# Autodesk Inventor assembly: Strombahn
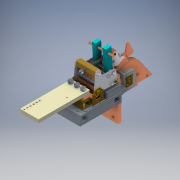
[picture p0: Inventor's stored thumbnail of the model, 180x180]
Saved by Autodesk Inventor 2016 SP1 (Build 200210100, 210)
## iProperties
Title: Strombahn
Comments: HSLT
Company: Mayer & Müller AG Schaltgeräte
Created: 2005-12
Part Number: 340853 Strombahn
Document SubType Name: Assembly
Designer: I.Baliuc
Manufacturer: Standard
Standards Organization: Custom
Description: Strombahn
Mass: 12082.3 g
Surface Area: 8161.82 cm^2
Volume: 2037 cm^3
Density: 5.93143 g/cm^3
Zweck: Vorkontakt HSLT
dX*dY*dZ: 110 x 526 x 296
Flaeche: 816182
Volumen: 2036999
Author: T.Messerschmitt
Revision Number: 340853
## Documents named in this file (62)
- D:\Inventor-Tools Tutorial\Baugruppen\340853 Strombahn.iam
- D:\Inventor-Tools Tutorial\Baugruppen\362517.iam
- D:\Inventor-Tools Tutorial\Bauteile\3\36\364835.ipt
- D:\Inventor-Tools Tutorial\Bauteile\3\36\366297.ipt
- D:\Inventor-Tools Tutorial\Bauteile\3\35\357419.ipt
- D:\Inventor-Tools Tutorial\Bauteile\3\35\356512.ipt
- D:\Inventor-Tools Tutorial\ContentCenter\DIN 125-1 A10 - St vz.ipt
- D:\Inventor-Tools Tutorial\Bauteile\3\36\361090.ipt
- D:\Inventor-Tools Tutorial\Bauteile\3\35\355018.ipt
- D:\Inventor-Tools Tutorial\Bauteile\3\35\356531.ipt
- D:\Inventor-Tools Tutorial\Bauteile\3\35\355073.ipt
- D:\Inventor-Tools Tutorial\Bauteile\3\35\356532.ipt
- D:\Inventor-Tools Tutorial\Bauteile\3\35\355104.ipt
- D:\Inventor-Tools Tutorial\Baugruppen\3\34\340827.iam
- D:\Inventor-Tools Tutorial\Bauteile\3\36\361570.ipt
- D:\Inventor-Tools Tutorial\ContentCenter\DIN 912 - M8x30 - 8.8 vz.ipt
- D:\Inventor-Tools Tutorial\ContentCenter\DIN 912 - M6x16 - A2.ipt
- D:\Inventor-Tools Tutorial\ContentCenter\DIN 934 - M8 - 8 vz.ipt
- D:\Inventor-Tools Tutorial\ContentCenter\DIN 127 - A6 - FSt vz.ipt
- D:\Inventor-Tools Tutorial\Bauteile\3\35\355017.ipt
- D:\Inventor-Tools Tutorial\ContentCenter\DIN 914 - M5x10 - 45H vz.ipt
- D:\Inventor-Tools Tutorial\ContentCenter\DIN 127 - A10 - FSt vz.ipt
- D:\Inventor-Tools Tutorial\ContentCenter\DIN 931-1 - M10x45 - 8.8 vz.ipt
- D:\Inventor-Tools Tutorial\Bauteile\3\35\357400.ipt
- D:\Inventor-Tools Tutorial\ContentCenter\DIN 912 - M8x12 - 8.8 vz.ipt
- D:\Inventor-Tools Tutorial\Baugruppen\3\34\340832.iam
- D:\Inventor-Tools Tutorial\Bauteile\3\37\378316.ipt
- D:\Inventor-Tools Tutorial\Bauteile\3\35\350860.ipt
- D:\Inventor-Tools Tutorial\Bauteile\3\35\350825_zu.ipt
- D:\Inventor-Tools Tutorial\ContentCenter\DIN 439 - M8 - 04 vz.ipt
- D:\Inventor-Tools Tutorial\ContentCenter\DIN 7991 - M6x16 - A2.ipt
- D:\Inventor-Tools Tutorial\ContentCenter\DIN 933 - M8x12 - 8.8 vz.ipt
- D:\Inventor-Tools Tutorial\ContentCenter\DIN 934 - M6 - 8 vz.ipt
- D:\Inventor-Tools Tutorial\ContentCenter\DIN 7991 - M10x40 - A2.ipt
- D:\Inventor-Tools Tutorial\Bauteile\3\36\360212_s.ipt
- D:\Inventor-Tools Tutorial\Bauteile\Ringfeder_N9.ipt
- D:\Inventor-Tools Tutorial\Bauteile\Ringfeder_N7.ipt
- D:\Inventor-Tools Tutorial\ContentCenter\DIN 912 - M6x35 - 8.8 vz.ipt
- D:\Inventor-Tools Tutorial\Bauteile\3\35\356578.ipt
- D:\Inventor-Tools Tutorial\Baugruppen\3\34\340855.iam
- D:\Inventor-Tools Tutorial\Baugruppen\3\34\340838.iam
- D:\Inventor-Tools Tutorial\Bauteile\3\36\366298.ipt
- D:\Inventor-Tools Tutorial\Bauteile\SPERRZSCHR_M8x12.ipt
- D:\Inventor-Tools Tutorial\Bauteile\SPERRZSCHR_M6x10.ipt
- D:\Inventor-Tools Tutorial\Bauteile\3\35\350822_C1.ipt
- D:\Inventor-Tools Tutorial\ContentCenter\DIN 6912 - M8x16 - A2.ipt
- D:\Inventor-Tools Tutorial\Bauteile\3\35\350822_C2.ipt
- D:\Inventor-Tools Tutorial\ContentCenter\DIN 127 - A6 - A2.ipt
- D:\Inventor-Tools Tutorial\Bauteile\3\36\360211.ipt
- D:\Inventor-Tools Tutorial\ContentCenter\DIN 9021 - 6.4 - A2.ipt
- D:\Inventor-Tools Tutorial\Baugruppen\3\34\340833.iam
- D:\Inventor-Tools Tutorial\Bauteile\3\37\378299.ipt
- D:\Inventor-Tools Tutorial\Bauteile\3\37\378333.ipt
- D:\Inventor-Tools Tutorial\Bauteile\3\36\361600.ipt
- D:\Inventor-Tools Tutorial\Baugruppen\3\34\342333.iam
- D:\Inventor-Tools Tutorial\ContentCenter\DIN 127 - A8 - FSt vz.ipt
- D:\Inventor-Tools Tutorial\ContentCenter\DIN 125-1 A10 - Ms.ipt
- D:\Inventor-Tools Tutorial\Bauteile\HMR_H10.ipt
- D:\Inventor-Tools Tutorial\Baugruppen\3\34\340831.iam
- D:\Inventor-Tools Tutorial\ContentCenter\DIN 125-1 A6 - St vz.ipt
- D:\Inventor-Tools Tutorial\ContentCenter\DIN 912 - M6x20 - A2.ipt
- D:\Inventor-Tools Tutorial\ContentCenter\DIN 912 - M6x25 - A2.ipt
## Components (126 placed, 67 different names)
1. 340838 - Hauptkontakt (mitte) [sub-assembly] — Einfügen:134, Einfügen:135
2. 340860 - Schiene, unten — Einfügen:94, Einfügen:95, Winkel:39, Winkel:46
3. 340831 - Stromschiene [sub-assembly] — Einfügen:89, Einfügen:90, Winkel:31, Einfügen:150, Einfügen:151, Winkel:62
4. 340832 - Vorkontakt [sub-assembly] — Einfügen:48, Einfügen:49, Tangential:1
5. 340833 - Funkenhorn, kompl. [sub-assembly] — Einfügen:70, Einfügen:73, Einfügen:74, Winkel:54, Winkel:63, Tangential:1
6. 340855 - Kontaktträger [sub-assembly] — Passend:24, Passend:25, Passend:26, Passend:27, Einfügen:48, Einfügen:49, Winkel:34, Winkel:53, Einfügen:158, Einfügen:159
7. 342333 - Spule, kompl. [sub-assembly] — Einfügen:66, Einfügen:67, Einfügen:68, Einfügen:69, Einfügen:70, Einfügen:73, Einfügen:74, Einfügen:76, Einfügen:89, Einfügen:90, Winkel:55, Winkel:56
8. 350825 - Stromband — Einfügen:22, Einfügen:23, Einfügen:94, Einfügen:95, Einfügen:134, Einfügen:135, Einfügen:139, Einfügen:140
9. 350822_C1 - Stromband — Einfügen:158, Einfügen:159, Fluchtend:4
10. 350822_C2 - Stromband — Fluchtend:4, Winkel:66
11. 355018 - Bolzen — Einfügen:24, Passend:22, Passend:23
12. 356531 - Bolzen — Einfügen:6
13. 355073 - Bolzen — Passend:5, Passend:40, Passend:41
14. 355017 - Bolzen — Einfügen:25, Passend:20, Passend:21, Passend:24, Passend:25
15. 355104 - Bolzen — Einfügen:145
16. 356512 - Gewindestange — Einfügen:17, Passend:32, Einfügen:119
17. 356578 - Bolzen — Passend:26, Passend:27, Passend:28, Passend:29
18. 356532 - Bolzen — Einfügen:5, Passend:8, Passend:31, Passend:43
19. 357400 - Welle — Passend:15, Passend:32
20. 357419 - Federsockel — Einfügen:17, Passend:28, Passend:29, Winkel:52, Fluchtend:3
21. 360212 - Druckfeder T1
22. 360212 - Druckfeder T2
23. 361600 - Gewindeplatte — Einfügen:68, Einfügen:69
24. 362469 - Isolator [sub-assembly] — Einfügen:148, Einfügen:149, Einfügen:150, Einfügen:151, Passend:51, Passend:52, Einfügen:152, Winkel:57
25. 364835 - Gewindeplatte — Einfügen:3, Passend:1
26. 366297 - Vierkantrohr — Einfügen:3, Passend:1, Einfügen:22, Einfügen:23, Einfügen:148, Einfügen:149, Winkel:58
27. 366298 - Distanzbuchse:1 — Passend:40, Passend:41
28. 378299 - Isolierplatte — Einfügen:66, Einfügen:67
29. DIN 125-1  A A 10.5:2
30. DIN 125-1  A A 10.5:1
31. DIN 912 - M6 x 20 - V2A:1 — Winkel:33, Winkel:34
32. DIN 912 - M6 x 25 - V2A:2 — Winkel:33, Winkel:53
33. DIN 914  M5 x 10:1 — Winkel:52, Fluchtend:3
34. Sperrzahnschraube_M6x10:1 — Winkel:43
35. Sperrzahnschraube_M6x10:2 — Winkel:60, Winkel:61
36. Sperrzahnschraube - M8x12:1 — Winkel:43, Winkel:64
37. Sperrzahnschraube - M8x12:2 — Winkel:60
38. DIN 933  - ersetzt durch DIN EN 24 017 M8 x 12:1 — Winkel:64, Winkel:65
39. DIN 933  - ersetzt durch DIN EN 24 017 M8 x 12:2 — Winkel:65
40. DIN 6912  M8 x 16:1 — Winkel:66
41. 361570_Kontaktträgerseitenteil:1 — Einfügen:5, Einfügen:6, Passend:5, Passend:15, Einfügen:24, Einfügen:25, Einfügen:152, Winkel:44, Winkel:45, Winkel:47, Winkel:48
42. 361570 - Kontaktträgerseitenteil:2 — Winkel:49, Winkel:50, Winkel:51, Winkel:61
43. DIN 7991 - ersetzt durch DIN EN ISO 10642  M10 x 40:2 — Winkel:31, Winkel:62
44. DIN 7991 - ersetzt durch DIN EN ISO 10642  M10 x 40:3
45. DIN 912  - ersetzt durch DIN EN ISO 4762 M8 x 30:1 — Winkel:58
46. DIN 934  - ersetzt durch DIN EN 24 032/28 673/28 674 M8:1 — Winkel:57
47. DIN 127 - zurückgezogen A 8:1
48. DIN 912  - ersetzt durch DIN EN ISO 4762 M8 x 30:2
49. DIN 934  - ersetzt durch DIN EN 24 032/28 673/28 674 M8:2
50. DIN 127 - zurückgezogen A 8:2
51. 361090_Lasche:1 — Einfügen:8, Passend:8, Passend:31
52. 361090:2 — Einfügen:96
53. 340827_Hauptkontakt:1 [sub-assembly] — Einfügen:8, Einfügen:139, Einfügen:140
54. 340827 - DC Hauptkontakt:2 [sub-assembly] — Passend:57
55. DIN 439-2  - ersetzt durch DIN EN 24 035/28 675 M8:2 — Einfügen:119, Winkel:44
56. DIN 439-2  - ersetzt durch DIN EN 24 035/28 675 M8:3
57. DIN 125-1  A A 10.5:6
58. DIN 127 - zurückgezogen A 10:4
59. DIN 931-1  - ersetzt durch DIN EN 24 014 M10 x 45:1 — Winkel:39
60. DIN 125-1  A A 10.5:7
61. DIN 127 - zurückgezogen A 10:5
62. DIN 931-1  - ersetzt durch DIN EN 24 014 M10 x 45:2
63. DIN 125-1  A A 10.5:8
64. DIN 127 - zurückgezogen A 10:6
65. DIN 931-1  - ersetzt durch DIN EN 24 014 M10 x 45:3 — Winkel:46
66. DIN 125-1  A A 6.4:11
67. DIN 127 - zurückgezogen A 6:13
68. DIN 934  - ersetzt durch DIN EN 24 032/28 673/28 674 M6:1 — Winkel:36, Winkel:45
69. DIN 912  - ersetzt durch DIN EN ISO 4762 M6 x 35:1 — Winkel:49
70. DIN 125-1  A A 6.4:13
71. DIN 127 - zurückgezogen A 6:15
72. DIN 934  - ersetzt durch DIN EN 24 032/28 673/28 674 M6:3 — Winkel:36, Winkel:37, Winkel:47
73. DIN 912  - ersetzt durch DIN EN ISO 4762 M6 x 35:3 — Winkel:32, Winkel:50
74. DIN 125-1  A A 6.4:15
75. DIN 127 - zurückgezogen A 6:17
76. DIN 934  - ersetzt durch DIN EN 24 032/28 673/28 674 M6:5 — Winkel:37, Winkel:48
77. DIN 912  - ersetzt durch DIN EN ISO 4762 M6 x 35:5 — Winkel:32, Winkel:51
78. DIN 125-1  A A 6.4:12
79. DIN 127 - zurückgezogen A 6:14
80. DIN 934  - ersetzt durch DIN EN 24 032/28 673/28 674 M6:2
81. DIN 912  - ersetzt durch DIN EN ISO 4762 M6 x 35:2
82. DIN 125-1  A A 6.4:14
83. DIN 127 - zurückgezogen A 6:16
84. DIN 934  - ersetzt durch DIN EN 24 032/28 673/28 674 M6:4
85. DIN 912  - ersetzt durch DIN EN ISO 4762 M6 x 35:4
86. DIN 125-1  A A 6.4:16
87. DIN 127 - zurückgezogen A 6:18
88. DIN 934  - ersetzt durch DIN EN 24 032/28 673/28 674 M6:6
89. DIN 912  - ersetzt durch DIN EN ISO 4762 M6 x 35:6
90. DIN 912  - ersetzt durch DIN EN ISO 4762 M8 x 12:1 — Passend:58
91. 360211_Druckfeder:4 — Passend:57, Passend:58
92. DIN 912  - ersetzt durch DIN EN ISO 4762 M8 x 12:2
93. 360211 - Druckfeder:5
94. DIN 912  - ersetzt durch DIN EN ISO 4762 M8 x 12:3
95. 360211 - Druckfeder:6
96. Ringfeder - N9:1 — Passend:20, Passend:21
97. Ringfeder - N9:2
98. Ringfeder - N7:1 — Passend:22, Passend:23
99. Ringfeder - N7:2
100. DIN 127 - zurückgezogen A 6:7
101. DIN 127 - zurückgezogen A 6:8
102. Halbmondring - H10:1
103. Halbmondring - H10:2
104. DIN 7991 - ersetzt durch DIN EN ISO 10642  M6 x 16:3 — Winkel:63
105. DIN 7991 - ersetzt durch DIN EN ISO 10642  M6 x 16:4 — Winkel:54
106. DIN 912  - ersetzt durch DIN EN ISO 4762 M6 x 16:2 — Winkel:56
107. DIN 127 - zurückgezogen A 6:3
108. DIN 912  - ersetzt durch DIN EN ISO 4762 M6 x 16:3
109. DIN 127 - zurückgezogen A 6:4
110. DIN 912  - ersetzt durch DIN EN ISO 4762 M6 x 16:4
111. DIN 127 - zurückgezogen A 6:5
112. DIN 912  - ersetzt durch DIN EN ISO 4762 M6 x 16:5
113. DIN 127 - zurückgezogen A 6:6
114. DIN 912  - ersetzt durch DIN EN ISO 4762 M6 x 25:4 — Winkel:55
115. DIN 127 - zurückgezogen A 6:1
116. DIN 9021 6.4:1
117. 378333 - Isolierhülse:1 — Einfügen:76
118. DIN 912  - ersetzt durch DIN EN ISO 4762 M6 x 25:5
119. DIN 127 - zurückgezogen A 6:2
120. DIN 9021 6.4:3
121. 378333_Isolierhülse:2
122. 360211_Druckfeder:1 — Passend:51, Passend:52
123. 360211 - Druckfeder:2
124. 360211 - Druckfeder:3
125. 378316 - Anschlaghebel — Passend:43, Einfügen:96, Einfügen:145
126. 378316:2
## Component patterns: 361570 - Kontaktträgerseitenteil (2 elements), DIN 7991 - M10 x 40 (2 elements), Schraube_01 (2 elements), 361090 - Lasche (2 elements), 340827 - Hauptkontakt (2 elements), DIN 439 - M8 (2 elements), KA 8 (3 elements), KA 9 (2 elements), KA 10 (3 elements), Ringfeder_N9 (2 elements), Ringfeder_N7 (2 elements), DIN 125-1 A6.4 (2 elements), Halbmondring_H10 (2 elements), 360211 - Druckfeder (3 elements), 378316 - Anschlaghebel (2 elements)
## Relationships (93: Insert 37, Angle 30, Mate 23, Flush 2, Tangent 1)
- Einfügen:3 [Insert]: 364835 - Gewindeplatte ↔ 366297 - Vierkantrohr
- Passend:1 [Mate]: 364835 - Gewindeplatte ↔ 366297 - Vierkantrohr
- Einfügen:5 [Insert]: 356532 - Bolzen ↔ 361570_Kontaktträgerseitenteil:1
- Einfügen:6 [Insert]: 356531 - Bolzen ↔ 361570_Kontaktträgerseitenteil:1
- Passend:5 [Mate]: 355073 - Bolzen ↔ 361570_Kontaktträgerseitenteil:1
- Einfügen:8 [Insert]: 361090_Lasche:1 ↔ 340827_Hauptkontakt:1
- Passend:8 [Mate]: 356532 - Bolzen ↔ 361090_Lasche:1
- Einfügen:17 [Insert]: 356512 - Gewindestange ↔ 357419 - Federsockel
- Passend:15 [Mate]: 357400 - Welle ↔ 361570_Kontaktträgerseitenteil:1
- Einfügen:22 [Insert]: 350825 - Stromband ↔ 366297 - Vierkantrohr
- Einfügen:23 [Insert]: 350825 - Stromband ↔ 366297 - Vierkantrohr
- Einfügen:24 [Insert]: 355018 - Bolzen ↔ 361570_Kontaktträgerseitenteil:1
- Einfügen:25 [Insert]: 355017 - Bolzen ↔ 361570_Kontaktträgerseitenteil:1
- Passend:20 [Mate]: 355017 - Bolzen ↔ Ringfeder - N9:1
- Passend:21 [Mate]: 355017 - Bolzen ↔ Ringfeder - N9:1
- Passend:22 [Mate]: 355018 - Bolzen ↔ Ringfeder - N7:1
- Passend:23 [Mate]: 355018 - Bolzen ↔ Ringfeder - N7:1
- Passend:24 [Mate]: 340855 - Kontaktträger ↔ 355017 - Bolzen
- Passend:25 [Mate]: 340855 - Kontaktträger ↔ 355017 - Bolzen
- Passend:26 [Mate]: 340855 - Kontaktträger ↔ 356578 - Bolzen
- Passend:27 [Mate]: 340855 - Kontaktträger ↔ 356578 - Bolzen
- Passend:28 [Mate]: 356578 - Bolzen ↔ 357419 - Federsockel
- Passend:29 [Mate]: 356578 - Bolzen ↔ 357419 - Federsockel
- Einfügen:48 [Insert]: 340832 - Vorkontakt ↔ 340855 - Kontaktträger
- Einfügen:49 [Insert]: 340832 - Vorkontakt ↔ 340855 - Kontaktträger
- Passend:31 [Mate]: 356532 - Bolzen ↔ 361090_Lasche:1
- Passend:32 [Mate]: 356512 - Gewindestange ↔ 357400 - Welle
- Einfügen:66 [Insert]: 342333 - Spule, kompl. ↔ 378299 - Isolierplatte
- Einfügen:67 [Insert]: 342333 - Spule, kompl. ↔ 378299 - Isolierplatte
- Einfügen:68 [Insert]: 342333 - Spule, kompl. ↔ 361600 - Gewindeplatte
- Einfügen:69 [Insert]: 342333 - Spule, kompl. ↔ 361600 - Gewindeplatte
- Einfügen:70 [Insert]: 340833 - Funkenhorn, kompl. ↔ 342333 - Spule, kompl.
- Einfügen:73 [Insert]: 340833 - Funkenhorn, kompl. ↔ 342333 - Spule, kompl.
- Einfügen:74 [Insert]: 340833 - Funkenhorn, kompl. ↔ 342333 - Spule, kompl.
- Einfügen:76 [Insert]: 342333 - Spule, kompl. ↔ 378333 - Isolierhülse:1
- Passend:40 [Mate]: 355073 - Bolzen ↔ 366298 - Distanzbuchse:1
- Passend:41 [Mate]: 355073 - Bolzen ↔ 366298 - Distanzbuchse:1
- Einfügen:89 [Insert]: 340831 - Stromschiene ↔ 342333 - Spule, kompl.
- Einfügen:90 [Insert]: 340831 - Stromschiene ↔ 342333 - Spule, kompl.
- Einfügen:94 [Insert]: 340860 - Schiene, unten ↔ 350825 - Stromband
- Einfügen:95 [Insert]: 340860 - Schiene, unten ↔ 350825 - Stromband
- Passend:43 [Mate]: 356532 - Bolzen ↔ 378316 - Anschlaghebel
- Einfügen:96 [Insert]: 361090:2 ↔ 378316 - Anschlaghebel
- Einfügen:119 [Insert]: 356512 - Gewindestange ↔ DIN 439-2  - ersetzt durch DIN EN 24 035/28 675 M8:2
- Winkel:31 [Angle]: 340831 - Stromschiene ↔ DIN 7991 - ersetzt durch DIN EN ISO 10642  M10 x 40:2
- Einfügen:134 [Insert]: 340838 - Hauptkontakt (mitte) ↔ 350825 - Stromband
- Einfügen:135 [Insert]: 340838 - Hauptkontakt (mitte) ↔ 350825 - Stromband
- Winkel:32 [Angle]: DIN 912  - ersetzt durch DIN EN ISO 4762 M6 x 35:3 ↔ DIN 912  - ersetzt durch DIN EN ISO 4762 M6 x 35:5
- Winkel:33 [Angle]: DIN 912 - M6 x 20 - V2A:1 ↔ DIN 912 - M6 x 25 - V2A:2
- Winkel:34 [Angle]: 340855 - Kontaktträger ↔ DIN 912 - M6 x 20 - V2A:1
- Einfügen:139 [Insert]: 350825 - Stromband ↔ 340827_Hauptkontakt:1
- Einfügen:140 [Insert]: 350825 - Stromband ↔ 340827_Hauptkontakt:1
- Winkel:36 [Angle]: DIN 934  - ersetzt durch DIN EN 24 032/28 673/28 674 M6:1 ↔ DIN 934  - ersetzt durch DIN EN 24 032/28 673/28 674 M6:3
- Winkel:37 [Angle]: DIN 934  - ersetzt durch DIN EN 24 032/28 673/28 674 M6:3 ↔ DIN 934  - ersetzt durch DIN EN 24 032/28 673/28 674 M6:5
- Winkel:39 [Angle]: 340860 - Schiene, unten ↔ DIN 931-1  - ersetzt durch DIN EN 24 014 M10 x 45:1
- Einfügen:145 [Insert]: 355104 - Bolzen ↔ 378316 - Anschlaghebel
- Einfügen:148 [Insert]: 362469 - Isolator ↔ 366297 - Vierkantrohr
- Einfügen:149 [Insert]: 362469 - Isolator ↔ 366297 - Vierkantrohr
- Einfügen:150 [Insert]: 340831 - Stromschiene ↔ 362469 - Isolator
- Einfügen:151 [Insert]: 340831 - Stromschiene ↔ 362469 - Isolator
- Passend:51 [Mate]: 362469 - Isolator ↔ 360211_Druckfeder:1
- Passend:52 [Mate]: 362469 - Isolator ↔ 360211_Druckfeder:1
- Einfügen:152 [Insert]: 362469 - Isolator ↔ 361570_Kontaktträgerseitenteil:1
- Winkel:43 [Angle]: Sperrzahnschraube_M6x10:1 ↔ Sperrzahnschraube - M8x12:1
- Winkel:44 [Angle]: 361570_Kontaktträgerseitenteil:1 ↔ DIN 439-2  - ersetzt durch DIN EN 24 035/28 675 M8:2
- Winkel:45 [Angle]: 361570_Kontaktträgerseitenteil:1 ↔ DIN 934  - ersetzt durch DIN EN 24 032/28 673/28 674 M6:1
- Winkel:46 [Angle]: 340860 - Schiene, unten ↔ DIN 931-1  - ersetzt durch DIN EN 24 014 M10 x 45:3
- Winkel:47 [Angle]: 361570_Kontaktträgerseitenteil:1 ↔ DIN 934  - ersetzt durch DIN EN 24 032/28 673/28 674 M6:3
- Winkel:48 [Angle]: 361570_Kontaktträgerseitenteil:1 ↔ DIN 934  - ersetzt durch DIN EN 24 032/28 673/28 674 M6:5
- Winkel:49 [Angle]: 361570 - Kontaktträgerseitenteil:2 ↔ DIN 912  - ersetzt durch DIN EN ISO 4762 M6 x 35:1
- Winkel:50 [Angle]: 361570 - Kontaktträgerseitenteil:2 ↔ DIN 912  - ersetzt durch DIN EN ISO 4762 M6 x 35:3
- Winkel:51 [Angle]: 361570 - Kontaktträgerseitenteil:2 ↔ DIN 912  - ersetzt durch DIN EN ISO 4762 M6 x 35:5
- Winkel:52 [Angle]: 357419 - Federsockel ↔ DIN 914  M5 x 10:1
- Winkel:53 [Angle]: 340855 - Kontaktträger ↔ DIN 912 - M6 x 25 - V2A:2
- Winkel:54 [Angle]: 340833 - Funkenhorn, kompl. ↔ DIN 7991 - ersetzt durch DIN EN ISO 10642  M6 x 16:4
- Winkel:55 [Angle]: 342333 - Spule, kompl. ↔ DIN 912  - ersetzt durch DIN EN ISO 4762 M6 x 25:4
- Winkel:56 [Angle]: 342333 - Spule, kompl. ↔ DIN 912  - ersetzt durch DIN EN ISO 4762 M6 x 16:2
- Winkel:57 [Angle]: 362469 - Isolator ↔ DIN 934  - ersetzt durch DIN EN 24 032/28 673/28 674 M8:1
- Winkel:58 [Angle]: 366297 - Vierkantrohr ↔ DIN 912  - ersetzt durch DIN EN ISO 4762 M8 x 30:1
- Winkel:60 [Angle]: Sperrzahnschraube_M6x10:2 ↔ Sperrzahnschraube - M8x12:2
- Winkel:61 [Angle]: Sperrzahnschraube_M6x10:2 ↔ 361570 - Kontaktträgerseitenteil:2
- Winkel:62 [Angle]: 340831 - Stromschiene ↔ DIN 7991 - ersetzt durch DIN EN ISO 10642  M10 x 40:2
- Passend:57 [Mate]: 340827 - DC Hauptkontakt:2 ↔ 360211_Druckfeder:4
- Passend:58 [Mate]: DIN 912  - ersetzt durch DIN EN ISO 4762 M8 x 12:1 ↔ 360211_Druckfeder:4
- Winkel:63 [Angle]: 340833 - Funkenhorn, kompl. ↔ DIN 7991 - ersetzt durch DIN EN ISO 10642  M6 x 16:3
- Fluchtend:3 [Flush]: 357419 - Federsockel ↔ DIN 914  M5 x 10:1
- Einfügen:158 [Insert]: 340855 - Kontaktträger ↔ 350822_C1 - Stromband
- Einfügen:159 [Insert]: 340855 - Kontaktträger ↔ 350822_C1 - Stromband
- Fluchtend:4 [Flush]: 350822_C1 - Stromband ↔ 350822_C2 - Stromband
- Winkel:64 [Angle]: Sperrzahnschraube - M8x12:1 ↔ DIN 933  - ersetzt durch DIN EN 24 017 M8 x 12:1
- Winkel:65 [Angle]: DIN 933  - ersetzt durch DIN EN 24 017 M8 x 12:1 ↔ DIN 933  - ersetzt durch DIN EN 24 017 M8 x 12:2
- Winkel:66 [Angle]: 350822_C2 - Stromband ↔ DIN 6912  M8 x 16:1
- Tangential:1: 340832 - Vorkontakt ↔ 340833 - Funkenhorn, kompl.
